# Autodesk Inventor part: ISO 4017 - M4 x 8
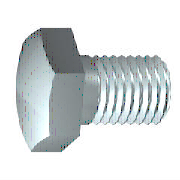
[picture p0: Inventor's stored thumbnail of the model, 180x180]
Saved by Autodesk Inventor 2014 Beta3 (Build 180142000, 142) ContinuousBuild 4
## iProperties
IsCustomPart: 0
Created: 2010-02
Part Number: ISO 4017 - M4 x 8
Material: Stainless Steel, 440C
Description: Hexagon head screws
Document SubType Name: Modeling
Standard: ISO 4017
Designer: Thom Tremblay
Standard Revision: Third edition 1999-08-15
Standards Organization: ISO
Language: en-US
Size Designation: M4 x 8
Categories: <MemberInstance><Categories><Category DisplayName="Fasteners" InternalName="e4da775c-781d-43d5-af7c-5136215cf5a6" Mnemonic="FSTN"><Category DisplayName="Bolts"
Density: 7.75 g/cm^3
Appearance: Steel
Author: Thom Tremblay
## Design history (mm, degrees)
sketch "Sketch1"
  geometry: L1 (0, 3.015)-(0, 2); L2 (2.1, 2)-(8, 2); L3 (8, 2)-(8, 0); L4 (8, 0)-(-0.4, 0); L5 (-2.08, 0)-(9.68, 0) reference; L6 (-0.4, 0)-(-0.4, 3.015); L7 (-0.4, 3.015)-(0, 3.015); L8 (2.1, 2)-(1.67, 2); L9 (1.67, 2)-(0, 2); L10 (0, -0.603)-(0, 3.618) reference
  constraints: 16 end point, 2 collinear, 2 perpendicular, 1 parallel
  dimensions: "d0" = 8 distance between parallel lines of L3 L1 (= NLG); "d1" = 5.9 distance from line of L2.start L3 (= GEL); "d2" = 4 diameter of L2 L4 (= GD); "d9" = 0.4001 distance between parallel lines of L6 L1 (computed from SD); "d10" = 6.03 diameter of L7 L4 (= SD2); "d13" = 0.42952 distance of L2.start L8.end (computed from GAL); "d14" = 4 diameter of L9 L4 (= BDM)
revolve "Body" sketch "Sketch1" stored, may be unused: angle "d12" = 90 deg
sketch "Sketch2"
  geometry: L1 (0, 4.041)-(3.5, 2.021); L2 (3.5, 2.021)-(3.5, -2.021); L3 (3.5, -2.021)-(0, -4.041); L4 (0, -4.041)-(-3.5, -2.021); L5 (-3.5, -2.021)-(-3.5, 2.021); L6 (-3.5, 2.021)-(0, 4.041); 2 further points
  constraints: 12 end point, 1 coincident, 1 vertical, 11 other
  dimensions: "d11" = 7 distance between parallel lines of L5 L2 (= SW)
extrude "Head" join sketch "Sketch2" distance "d3" = 2.4 (= KOH - SD); taper "d4" = 0 deg
sketch "Sketch4"
  geometry: L1 (-2.8, 3.5)-(-2.8, 4.041); L2 (-2.8, 4.041)-(-2.487, 4.041); L3 (-2.487, 4.041)-(-2.8, 3.5); L4 (-3.28, 0)-(0.08, 0) reference; L5 (-0.4, 4.041)-(-2.8, 4.041) reference; L6 (-2.8, 2.021)-(-2.8, 4.041) reference
  constraints: 6 end point, 2 collinear, 1 perpendicular, 1 vertical
  dimensions: "d5" = 30 deg angle of L3 L1 (= ANG1); "d19" = 7 diameter of L1.start L4 (= SW0)
revolve "Chamfer1" sketch "Sketch4" stored, may be unused: angle "d21" = 90 deg
workplane "Work Plane1"
body "Solid1"
feature "Thread" dims "d15" = 5.9 (= GEL), "d16" = 0
chamfer "Chamfer2" distance "d6" = 0.42941 (= -0.5 x SPD + 0.5 x GD); stored, may be unused: second distance "d7" = 0.42952 (computed from GUL), angle "d55" = 45 deg
other parameters: "NLG" = 8 [user parameter; used in 1 equation term], "GD" = 4 (= NND) [user parameter; used in 2 equation terms], "BDM" = 4 (= NND) [user parameter; used in 1 equation term], "KOH" = 2.8 [user parameter; used in 1 equation term], "GEL" = 5.9 [user parameter; used in 2 equation terms], "SW" = 7 [user parameter; used in 2 equation terms], "SW0" = 7 (= SW) [user parameter; used in 1 equation term], "SPD" = 3.14117 (= NND - 1.2269 x PTC) [user parameter; used in 1 equation term], "SD2" = 6.03 [user parameter; used in 2 equation terms], "SD" = 0.4 [user parameter; used in 2 equation terms], "ANG1" = 30 deg [user parameter; used in 1 equation term], "GAL" = 0.42941 (= 0.61345 x PTC) [user parameter; used in 1 equation term], "GUL" = 0.42941 (= 0.61345 x PTC) [user parameter; used in 1 equation term], "d8" = 0, "RR" = 0.2 [user parameter], "d57" = 0, "d58" = 0, "TPU" = 14.28571 (computed from PTC) [user parameter], "GD1" = 3.14117 (= THREADDIA - 1.2269 x PTC) [user parameter], "THREADDIA" = 4 [user parameter; used in 1 equation term], "SDH" = 6.03 (= SD2) [user parameter], "SDHG" = 2.1 [user parameter], "TOA" = 30 deg [user parameter], "PTC" = 0.7 [user parameter; used in 5 equation terms], "NND" = 4 [user parameter; used in 3 equation terms], "E0" = 8.085 [user parameter]
